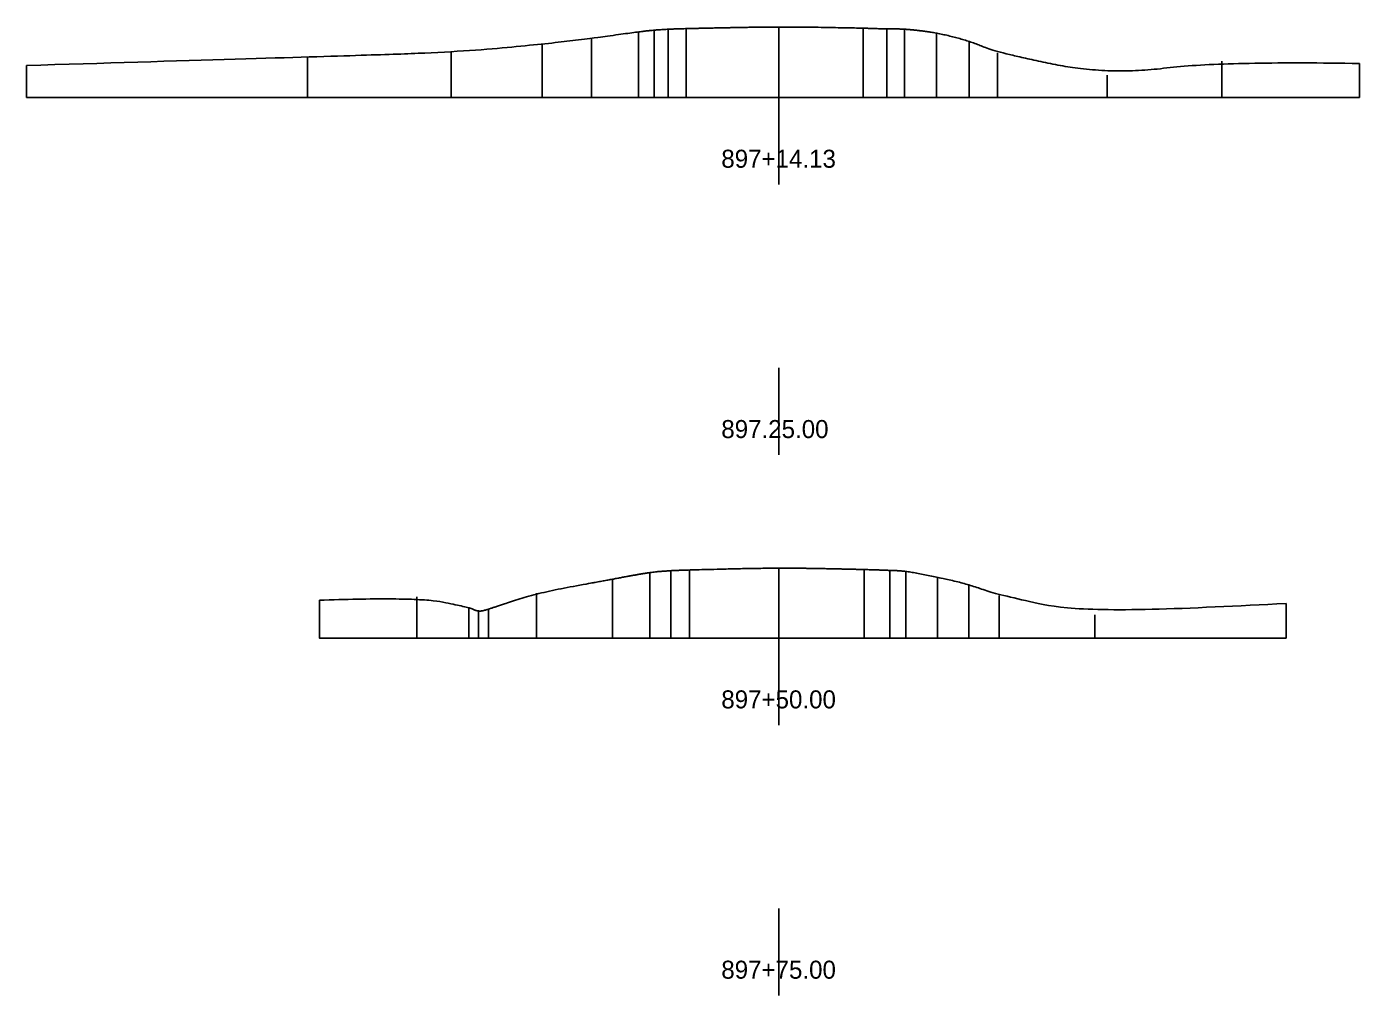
# Model space of a CAD drawing. Extents: x 1546689 to 1550004, y 741079 to 745265.
# Drawn here: x 1548243.05 to 1548280.01, y 743867.06 to 743893.94 of the extents above; entities that cross this region are included whole.
import ezdxf

# ---------------------------------------------------------------- set-up
doc = ezdxf.new("R2010")
doc.units = 0
doc.layers.add('UT_X_Electric_Cells', color=7, linetype='Continuous')
doc.layers.add('XS_P_Pavt_Layers', color=7, linetype='Continuous')

msp = doc.modelspace()

# ---------------------------------------------------------------- linework, layer by layer
at = {"layer": 'UT_X_Electric_Cells'}
for p, q in [((1548263.907, 743891.977), (1548263.907, 743889.564)), ((1548263.907, 743884.477), (1548263.907, 743882.064)), ((1548263.907, 743876.977), (1548263.907, 743874.564)), ((1548263.907, 743869.477), (1548263.907, 743867.064))]:
    msp.add_line(p, q, dxfattribs=at)
for points in [[(1548243.047, 743892.863), (1548250.837, 743893.099), (1548254.825, 743893.223), (1548257.349, 743893.453), (1548258.719, 743893.615), (1548260.015, 743893.797), (1548260.451, 743893.845), (1548260.843, 743893.871), (1548261.339, 743893.887), (1548263.907, 743893.941), (1548266.251, 743893.901), (1548266.909, 743893.875), (1548267.395, 743893.879), (1548268.281, 743893.775), (1548269.193, 743893.545), (1548269.977, 743893.217), (1548273.015, 743892.593), (1548276.199, 743892.983), (1548280.013, 743892.919)], [(1548251.167, 743878.029), (1548253.867, 743878.119), (1548255.315, 743877.831), (1548255.583, 743877.703), (1548255.859, 743877.777), (1548257.185, 743878.225), (1548259.295, 743878.609), (1548260.329, 743878.803), (1548260.919, 743878.849), (1548261.435, 743878.867), (1548263.907, 743878.929), (1548266.281, 743878.881), (1548266.989, 743878.855), (1548267.433, 743878.837), (1548268.315, 743878.665), (1548269.177, 743878.467), (1548270.025, 743878.161), (1548272.679, 743877.621), (1548277.979, 743877.937)]]:
    msp.add_open_spline(points, degree=2, dxfattribs=at)
at = {"layer": 'XS_P_Pavt_Layers'}
for p, q in [((1548263.907, 743891.977), (1548263.907, 743893.941)), ((1548263.907, 743876.977), (1548263.907, 743878.929))]:
    msp.add_line(p, q, dxfattribs=at)
for points in [[(1548263.907, 743891.977), (1548260.451, 743891.977), (1548260.451, 743893.845)], [(1548263.907, 743891.977), (1548260.843, 743891.977), (1548260.843, 743893.871)], [(1548263.907, 743891.977), (1548261.339, 743891.977), (1548261.339, 743893.887)], [(1548263.907, 743891.977), (1548266.251, 743891.977), (1548266.251, 743893.901)], [(1548263.907, 743891.977), (1548267.395, 743891.977), (1548267.395, 743893.879)], [(1548263.907, 743891.977), (1548266.909, 743891.977), (1548266.909, 743893.875)], [(1548263.907, 743891.977), (1548257.349, 743891.977), (1548257.349, 743893.453)], [(1548263.907, 743891.977), (1548258.719, 743891.977), (1548258.719, 743893.615)], [(1548263.907, 743891.977), (1548260.015, 743891.977), (1548260.015, 743893.797)], [(1548263.907, 743891.977), (1548268.281, 743891.977), (1548268.281, 743893.775)], [(1548263.907, 743891.977), (1548269.193, 743891.977), (1548269.193, 743893.545)], [(1548263.907, 743891.977), (1548250.837, 743891.977), (1548250.837, 743893.099)], [(1548263.907, 743891.977), (1548254.825, 743891.977), (1548254.825, 743893.223)], [(1548263.907, 743891.977), (1548269.977, 743891.977), (1548269.977, 743893.217)], [(1548263.907, 743891.977), (1548243.047, 743891.977), (1548243.047, 743892.863)], [(1548263.907, 743891.977), (1548276.199, 743891.977), (1548276.199, 743892.983)], [(1548263.907, 743891.977), (1548280.013, 743891.977), (1548280.013, 743892.919)], [(1548263.907, 743891.977), (1548273.015, 743891.977), (1548273.015, 743892.593)], [(1548263.907, 743876.977), (1548260.329, 743876.977), (1548260.329, 743878.803)], [(1548263.907, 743876.977), (1548260.919, 743876.977), (1548260.919, 743878.849)], [(1548263.907, 743876.977), (1548261.435, 743876.977), (1548261.435, 743878.867)], [(1548263.907, 743876.977), (1548266.281, 743876.977), (1548266.281, 743878.881)], [(1548263.907, 743876.977), (1548266.989, 743876.977), (1548266.989, 743878.855)], [(1548263.907, 743876.977), (1548267.433, 743876.977), (1548267.433, 743878.837)], [(1548263.907, 743876.977), (1548268.315, 743876.977), (1548268.315, 743878.665)], [(1548263.907, 743876.977), (1548259.295, 743876.977), (1548259.295, 743878.609)], [(1548263.907, 743876.977), (1548269.177, 743876.977), (1548269.177, 743878.467)], [(1548263.907, 743876.977), (1548251.167, 743876.977), (1548251.167, 743878.029)], [(1548263.907, 743876.977), (1548253.867, 743876.977), (1548253.867, 743878.119)], [(1548263.907, 743876.977), (1548257.185, 743876.977), (1548257.185, 743878.225)], [(1548263.907, 743876.977), (1548270.025, 743876.977), (1548270.025, 743878.161)], [(1548263.907, 743876.977), (1548277.979, 743876.977), (1548277.979, 743877.937)], [(1548263.907, 743876.977), (1548255.315, 743876.977), (1548255.315, 743877.831)], [(1548263.907, 743876.977), (1548255.583, 743876.977), (1548255.583, 743877.703)], [(1548263.907, 743876.977), (1548255.859, 743876.977), (1548255.859, 743877.777)], [(1548263.907, 743876.977), (1548272.679, 743876.977), (1548272.679, 743877.621)]]:
    msp.add_lwpolyline(points, dxfattribs=at)

# ---------------------------------------------------------------- texts
at = {"layer": 'UT_X_Electric_Cells'}
for s, p in [('897+14.13', (1548262.315, 743890.026)), ('897.25.00', (1548262.315, 743882.526)), ('897+50.00', (1548262.315, 743875.026)), ('897+75.00', (1548262.315, 743867.526))]:
    msp.add_text(s, height=0.5, dxfattribs=at).set_placement(p)

doc.saveas('drawing.dxf')
